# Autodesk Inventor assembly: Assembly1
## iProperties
Shininess: 64.0
Length Units: 11269
Angle Units: 11279
Time Units: 11290
Mass Units: 11283
Length Display Precision: 3
Angle Display Precision: 2
Compacted: True
Created: 2003-11
Part Number: Assembly1
Document SubType Name: Assembly
Designer: Owner
Manufacturer: Standard
Standards Organization: Custom
Density: 0.0
Volumn: 0.0
Area: 0.0
PropertySet Name: Model Information
Control State: 0
Master: False
Checked Out: False
Author: Owner
